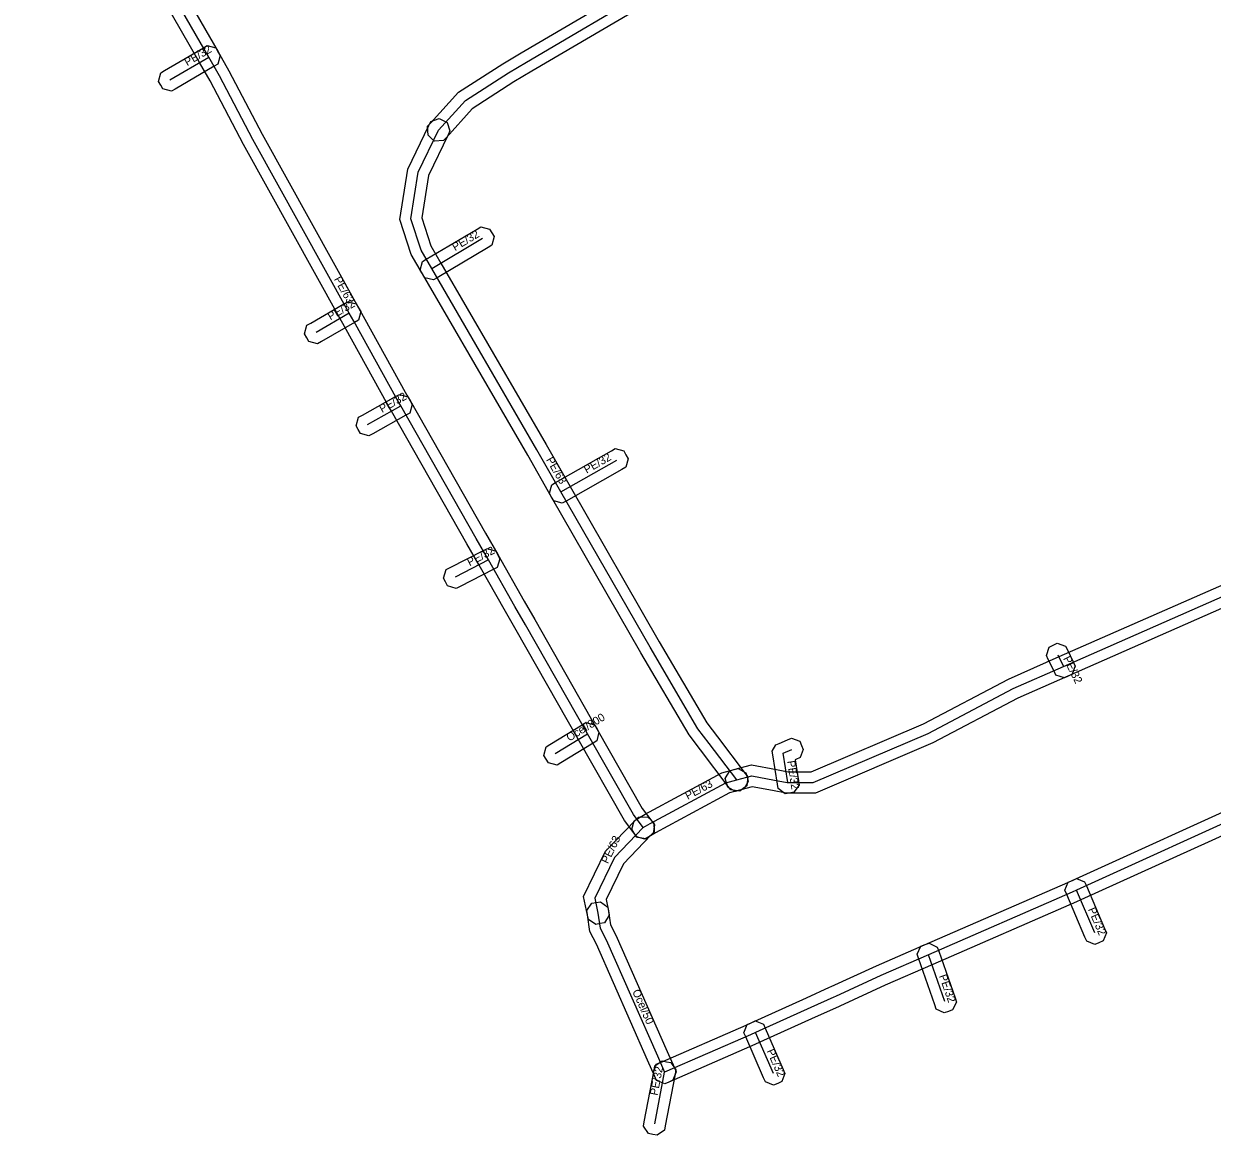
# Model space of a CAD drawing. Extents: x -574390 to -573768, y -1190959 to -1190603.
# Drawn here: x -574091.1 to -573979.8, y -1190806.5 to -1190702.4 of the extents above; entities that cross this region are included whole.
import ezdxf

# ---------------------------------------------------------------- set-up
doc = ezdxf.new("R2010")
doc.units = 0
for name, color, linetype in [('1', 7, 'Continuous'), ('24', 7, 'Continuous'), ('28', 7, 'Continuous'), ('30', 7, 'Continuous')]:
    doc.layers.add(name, color=color, linetype=linetype)

msp = doc.modelspace()

# ---------------------------------------------------------------- linework, layer by layer
at = {"layer": '1'}
for points in [[(-574082.082, -1190689.083), (-574072.923, -1190705.012), (-574071.904, -1190706.788), (-574068.77, -1190712.745), (-574059.755, -1190729.016), (-574059.335, -1190729.776), (-574055.23, -1190737.178), (-574054.932, -1190737.693), (-574047.861, -1190750.125), (-574046.721, -1190752.125), (-574044.241, -1190756.475), (-574043.251, -1190758.215), (-574037.431, -1190768.435), (-574033.173, -1190775.919), (-574032.282, -1190777.097), (-574032.032, -1190777.428), (-574032.146, -1190778.248), (-574032.477, -1190778.498), (-574032.808, -1190778.748), (-574033.628, -1190778.634), (-574033.878, -1190778.303), (-574034.847, -1190777.021), (-574039.169, -1190769.425), (-574044.989, -1190759.205), (-574045.979, -1190757.465), (-574048.459, -1190753.115), (-574049.599, -1190751.115), (-574056.668, -1190738.687), (-574056.97, -1190738.162), (-574061.085, -1190730.744), (-574061.505, -1190729.984), (-574070.53, -1190713.695), (-574073.656, -1190707.752), (-574074.657, -1190706.008), (-574083.818, -1190690.077)], [(-574031.616, -1190699.834), (-574043.513, -1190706.842), (-574045.195, -1190707.831), (-574049.097, -1190710.349), (-574051.529, -1190713.032), (-574051.807, -1190713.339), (-574052.635, -1190713.379), (-574052.942, -1190713.101), (-574053.249, -1190712.823), (-574053.289, -1190711.995), (-574053.011, -1190711.688), (-574050.403, -1190708.811), (-574046.245, -1190706.129), (-574044.527, -1190705.118), (-574032.624, -1190698.106)], [(-573977.067, -1190756.365), (-573993.297, -1190763.515), (-573997.995, -1190765.581), (-574005.96, -1190769.773), (-574016.947, -1190774.481), (-574019.532, -1190774.47), (-574019.707, -1190774.47), (-574020.978, -1190774.222), (-574022.867, -1190773.866), (-574024.053, -1190774.194), (-574024.452, -1190774.304), (-574025.173, -1190773.896), (-574025.284, -1190773.497), (-574025.394, -1190773.098), (-574024.986, -1190772.377), (-574024.587, -1190772.266), (-574022.953, -1190771.814), (-574020.602, -1190772.258), (-574019.511, -1190772.47), (-574017.353, -1190772.479), (-574006.82, -1190767.967), (-573998.865, -1190763.779), (-573994.103, -1190761.685), (-573977.873, -1190754.535)], [(-573974.492, -1190776.493), (-573992.077, -1190784.471), (-573992.504, -1190784.664), (-574005.951, -1190790.527), (-574010.421, -1190792.473), (-574014.657, -1190794.421), (-574014.803, -1190794.486), (-574016.968, -1190795.461), (-574022.156, -1190797.81), (-574022.622, -1190798.023), (-574030.68, -1190801.537), (-574031.06, -1190801.702), (-574031.831, -1190801.399), (-574031.997, -1190801.02), (-574032.162, -1190800.64), (-574031.859, -1190799.869), (-574031.48, -1190799.703), (-574023.438, -1190796.197), (-574022.984, -1190795.99), (-574017.792, -1190793.639), (-574015.623, -1190792.662), (-574015.483, -1190792.599), (-574011.239, -1190790.647), (-574006.749, -1190788.693), (-573993.316, -1190782.836), (-573992.903, -1190782.649), (-573975.308, -1190774.667)]]:
    msp.add_lwpolyline(points, dxfattribs=at)
for points in [[(-574078.292, -1190706.986), (-574077.935, -1190706.777), (-574074.295, -1190704.647), (-574073.938, -1190704.438), (-574073.136, -1190704.648), (-574072.927, -1190705.005), (-574072.718, -1190705.362), (-574072.928, -1190706.164), (-574073.285, -1190706.373), (-574076.925, -1190708.503), (-574077.282, -1190708.712), (-574078.084, -1190708.502), (-574078.293, -1190708.145), (-574078.502, -1190707.788)], [(-574024.865, -1190774.165), (-574025.116, -1190773.835), (-574027.715, -1190770.416), (-574028.791, -1190769.009), (-574033.315, -1190761.312), (-574041.668, -1190746.737), (-574043.907, -1190742.819), (-574053.765, -1190725.821), (-574054.818, -1190724), (-574055.886, -1190720.741), (-574055.124, -1190715.998), (-574053.172, -1190711.927), (-574052.993, -1190711.554), (-574052.211, -1190711.279), (-574051.837, -1190711.458), (-574051.464, -1190711.637), (-574051.189, -1190712.419), (-574051.368, -1190712.793), (-574053.196, -1190716.602), (-574053.834, -1190720.579), (-574052.982, -1190723.18), (-574052.035, -1190724.819), (-574042.173, -1190741.821), (-574039.932, -1190745.743), (-574031.585, -1190760.308), (-574027.129, -1190767.891), (-574026.125, -1190769.204), (-574023.524, -1190772.625), (-574023.273, -1190772.955), (-574023.385, -1190773.775), (-574023.715, -1190774.026), (-574024.045, -1190774.277)], [(-574053.766, -1190724.671), (-574053.41, -1190724.46), (-574048.64, -1190721.63), (-574048.284, -1190721.419), (-574047.481, -1190721.624), (-574047.27, -1190721.98), (-574047.059, -1190722.336), (-574047.264, -1190723.139), (-574047.62, -1190723.35), (-574052.39, -1190726.18), (-574052.746, -1190726.391), (-574053.549, -1190726.186), (-574053.76, -1190725.83), (-574053.971, -1190725.474)], [(-574059.771, -1190730.158), (-574060.129, -1190730.365), (-574063.239, -1190732.165), (-574063.598, -1190732.373), (-574064.398, -1190732.159), (-574064.605, -1190731.801), (-574064.813, -1190731.442), (-574064.599, -1190730.642), (-574064.241, -1190730.435), (-574061.131, -1190728.635), (-574060.772, -1190728.427), (-574059.972, -1190728.641), (-574059.765, -1190728.999), (-574059.557, -1190729.358)], [(-574059.76, -1190739.26), (-574059.398, -1190739.057), (-574056.288, -1190737.317), (-574055.927, -1190737.115), (-574055.13, -1190737.34), (-574054.927, -1190737.702), (-574054.725, -1190738.063), (-574054.95, -1190738.86), (-574055.312, -1190739.063), (-574058.422, -1190740.803), (-574058.783, -1190741.005), (-574059.58, -1190740.78), (-574059.783, -1190740.418), (-574059.985, -1190740.057)], [(-574041.654, -1190745.575), (-574041.294, -1190745.37), (-574036.064, -1190742.4), (-574035.704, -1190742.196), (-574034.905, -1190742.416), (-574034.7, -1190742.776), (-574034.496, -1190743.136), (-574034.716, -1190743.935), (-574035.076, -1190744.14), (-574040.306, -1190747.11), (-574040.666, -1190747.314), (-574041.465, -1190747.094), (-574041.67, -1190746.734), (-574041.874, -1190746.374)], [(-574046.763, -1190753.319), (-574047.131, -1190753.509), (-574050.251, -1190755.119), (-574050.619, -1190755.309), (-574051.409, -1190755.057), (-574051.599, -1190754.689), (-574051.789, -1190754.321), (-574051.537, -1190753.531), (-574051.169, -1190753.341), (-574048.049, -1190751.731), (-574047.681, -1190751.541), (-574046.891, -1190751.793), (-574046.701, -1190752.161), (-574046.511, -1190752.529)], [(-573993.525, -1190760.687), (-573993.342, -1190761.059), (-573992.802, -1190762.159), (-573992.62, -1190762.531), (-573992.887, -1190763.315), (-573993.259, -1190763.498), (-573993.631, -1190763.68), (-573994.415, -1190763.413), (-573994.598, -1190763.041), (-573995.138, -1190761.941), (-573995.32, -1190761.569), (-573995.053, -1190760.785), (-573994.681, -1190760.602), (-573994.309, -1190760.42)], [(-574042.194, -1190770.131), (-574041.84, -1190769.916), (-574038.82, -1190768.076), (-574038.466, -1190767.861), (-574037.661, -1190768.056), (-574037.446, -1190768.41), (-574037.231, -1190768.764), (-574037.426, -1190769.569), (-574037.78, -1190769.784), (-574040.8, -1190771.624), (-574041.154, -1190771.839), (-574041.959, -1190771.644), (-574042.174, -1190771.29), (-574042.389, -1190770.936)], [(-574020.454, -1190774.034), (-574020.518, -1190773.625), (-574020.948, -1190770.885), (-574021.001, -1190770.546), (-574020.67, -1190769.946), (-574020.355, -1190769.811), (-574019.565, -1190769.471), (-574019.185, -1190769.307), (-574018.415, -1190769.614), (-574018.251, -1190769.995), (-574018.087, -1190770.375), (-574018.394, -1190771.145), (-574018.775, -1190771.309), (-574018.852, -1190771.342), (-574018.542, -1190773.315), (-574018.478, -1190773.724), (-574018.966, -1190774.394), (-574019.375, -1190774.458), (-574019.784, -1190774.522)], [(-574033.946, -1190777.05), (-574033.589, -1190776.839), (-574032.912, -1190776.439), (-574025.732, -1190772.575), (-574024.58, -1190772.264), (-574024.18, -1190772.156), (-574023.462, -1190772.57), (-574023.354, -1190772.97), (-574023.246, -1190773.37), (-574023.66, -1190774.088), (-574024.06, -1190774.196), (-574024.988, -1190774.445), (-574031.928, -1190778.181), (-574032.571, -1190778.561), (-574032.928, -1190778.772), (-574033.73, -1190778.566), (-574033.941, -1190778.209), (-574034.152, -1190777.852)], [(-574032.073, -1190778.096), (-574032.36, -1190778.394), (-574034.949, -1190781.079), (-574036.572, -1190784.431), (-574036.351, -1190785.509), (-574036.267, -1190785.915), (-574036.723, -1190786.606), (-574037.129, -1190786.689), (-574037.535, -1190786.773), (-574038.226, -1190786.317), (-574038.309, -1190785.911), (-574038.668, -1190784.169), (-574036.611, -1190779.921), (-574033.8, -1190777.006), (-574033.513, -1190776.708), (-574032.684, -1190776.693), (-574032.386, -1190776.98), (-574032.088, -1190777.267)], [(-573991.537, -1190788.334), (-573991.7, -1190787.953), (-573993.41, -1190783.953), (-573993.573, -1190783.572), (-573993.264, -1190782.803), (-573992.883, -1190782.64), (-573992.502, -1190782.477), (-573991.733, -1190782.786), (-573991.57, -1190783.167), (-573989.86, -1190787.167), (-573989.697, -1190787.548), (-573990.006, -1190788.317), (-573990.387, -1190788.48), (-573990.768, -1190788.643)], [(-574036.406, -1190785.147), (-574036.342, -1190785.556), (-574036.147, -1190786.808), (-574035.656, -1190787.771), (-574030.848, -1190798.667), (-574030.165, -1190800.217), (-574029.998, -1190800.596), (-574030.298, -1190801.368), (-574030.677, -1190801.535), (-574031.056, -1190801.702), (-574031.828, -1190801.402), (-574031.995, -1190801.023), (-574032.678, -1190799.475), (-574037.464, -1190788.629), (-574038.073, -1190787.432), (-574038.318, -1190785.864), (-574038.382, -1190785.455), (-574037.893, -1190784.786), (-574037.484, -1190784.722), (-574037.075, -1190784.658)], [(-574005.627, -1190794.701), (-574005.764, -1190794.31), (-574007.294, -1190789.94), (-574007.431, -1190789.549), (-574007.071, -1190788.803), (-574006.68, -1190788.666), (-574006.289, -1190788.529), (-574005.543, -1190788.889), (-574005.406, -1190789.28), (-574003.876, -1190793.65), (-574003.739, -1190794.041), (-574004.099, -1190794.787), (-574004.49, -1190794.924), (-574004.881, -1190795.061)], [(-574021.641, -1190801.529), (-574021.807, -1190801.15), (-574023.487, -1190797.3), (-574023.652, -1190796.92), (-574023.349, -1190796.149), (-574022.97, -1190795.983), (-574022.59, -1190795.818), (-574021.819, -1190796.121), (-574021.653, -1190796.5), (-574019.973, -1190800.35), (-574019.808, -1190800.73), (-574020.111, -1190801.501), (-574020.49, -1190801.667), (-574020.87, -1190801.832)], [(-574033.07, -1190805.678), (-574032.992, -1190805.271), (-574032.062, -1190800.431), (-574031.984, -1190800.024), (-574031.298, -1190799.56), (-574030.891, -1190799.638), (-574030.484, -1190799.716), (-574030.02, -1190800.402), (-574030.098, -1190800.809), (-574031.028, -1190805.649), (-574031.106, -1190806.056), (-574031.792, -1190806.52), (-574032.199, -1190806.442), (-574032.606, -1190806.364)]]:
    msp.add_lwpolyline(points, close=True, dxfattribs=at)
at = {"layer": '24'}
for points in [[(-574052.27, -1190712.36), (-574049.75, -1190709.58), (-574045.72, -1190706.98), (-574044.02, -1190705.98), (-574032.12, -1190698.97), (-574018.83, -1190691.28), (-574010.79, -1190686.63), (-574001.67, -1190681.44), (-573999.27, -1190680.08), (-573995.75, -1190678.11), (-573983.73, -1190671.39), (-573975.99, -1190667.06), (-573969.47, -1190663.41), (-573965.82, -1190661.37), (-573959.87, -1190658), (-573951.88, -1190653.46), (-573950.37, -1190652.6), (-573943.33, -1190648.61), (-573936.84, -1190644.93), (-573934.69, -1190643.69), (-573928.142665, -1190639.934461)], [(-574033.08, -1190777.7), (-574034.01, -1190776.47), (-574038.3, -1190768.93), (-574044.12, -1190758.71), (-574045.11, -1190756.97), (-574047.59, -1190752.62), (-574048.73, -1190750.62), (-574055.8, -1190738.19), (-574056.1, -1190737.67), (-574060.21, -1190730.26), (-574060.63, -1190729.5), (-574069.65, -1190713.22), (-574072.78, -1190707.27), (-574073.79, -1190705.51), (-574082.95, -1190689.58), (-574087.13, -1190682.24), (-574091.12, -1190675.23)], [(-574077.43, -1190707.64), (-574073.79, -1190705.51)], [(-574024.32, -1190773.23), (-574026.92, -1190769.81), (-574027.96, -1190768.45), (-574032.45, -1190760.81), (-574040.8, -1190746.24), (-574043.04, -1190742.32), (-574052.9, -1190725.32), (-574053.9, -1190723.59), (-574054.86, -1190720.66), (-574054.16, -1190716.3), (-574052.27, -1190712.36)], [(-574060.63, -1190729.5), (-574063.74, -1190731.3)], [(-574058.91, -1190739.93), (-574055.8, -1190738.19)], [(-574040.8, -1190746.24), (-574035.57, -1190743.27)], [(-574024.32, -1190773.23), (-574022.91, -1190772.84), (-574020.79, -1190773.24), (-574019.61, -1190773.47), (-574019.53, -1190773.47), (-574017.15, -1190773.48), (-574006.39, -1190768.87), (-573998.43, -1190764.68), (-573993.7, -1190762.6), (-573977.47, -1190755.45)], [(-573994.24, -1190761.5), (-573993.7, -1190762.6)], [(-574033.08, -1190777.7), (-574032.42, -1190777.31), (-574025.36, -1190773.51), (-574024.32, -1190773.23)], [(-573974.9, -1190775.58), (-573992.49, -1190783.56), (-573992.91, -1190783.75), (-574006.35, -1190789.61), (-574010.83, -1190791.56), (-574015.07, -1190793.51), (-574015.213, -1190793.574), (-574017.38, -1190794.55), (-574022.57, -1190796.9), (-574023.03, -1190797.11), (-574031.08, -1190800.62)], [(-574033.08, -1190777.7), (-574035.78, -1190780.5), (-574037.62, -1190784.3), (-574037.33, -1190785.71)], [(-574037.33, -1190785.71), (-574037.11, -1190787.12), (-574036.56, -1190788.2), (-574031.763, -1190799.071), (-574031.08, -1190800.62)], [(-574020.89, -1190800.75), (-574022.57, -1190796.9)]]:
    msp.add_lwpolyline(points, dxfattribs=at)
at = {"layer": '28'}
for points in [[(-574052.9, -1190725.32), (-574048.13, -1190722.49)], [(-574047.59, -1190752.62), (-574050.71, -1190754.23)], [(-574041.32, -1190770.77), (-574038.3, -1190768.93)], [(-574019.53, -1190773.47), (-574019.96, -1190770.73), (-574019.17, -1190770.39)], [(-573990.78, -1190787.56), (-573992.49, -1190783.56)], [(-574004.82, -1190793.98), (-574006.35, -1190789.61)], [(-574032.01, -1190805.46), (-574031.08, -1190800.62)]]:
    msp.add_lwpolyline(points, dxfattribs=at)

# ---------------------------------------------------------------- texts
at = {"layer": '30'}
for s, rotation, p in [('PE/32', 30.33466996, (-574075.81, -1190706.375)), ('PE/32', 30.68029178, (-574050.715, -1190723.705)), ('PE/63', 298.98882252, (-574062.082904, -1190726.31671)), ('PE/32', 30.06132008, (-574062.385, -1190730.2)), ('PE/32', 29.22638161, (-574057.555, -1190738.86)), ('PE/63', 299.7448813, (-574042.205401, -1190743.230548)), ('PE/32', 29.59127368, (-574038.385, -1190744.555)), ('PE/32', 27.29489424, (-574049.35, -1190753.225)), ('PE/32', 296.14684124, (-573993.77, -1190761.85)), ('Ocel/800', 31.35276167, (-574040.01, -1190769.65)), ('PE/32', 278.91892862, (-574019.61167, -1190771.475171)), ('PE/63', 28.29107579, (-574028.909303, -1190775.112741)), ('PE/63', 64.16324578, (-574036.387878, -1190781.142356)), ('PE/32', 293.14670784, (-573991.435, -1190785.36)), ('PE/32', 289.29588617, (-574005.385, -1190791.595)), ('Ocel/50', 293.81022543, (-574034.132299, -1190793.048435)), ('PE/32', 293.5747062, (-574021.53, -1190798.625)), ('PE/32', 79.12325458, (-574031.745, -1190802.84))]:
    msp.add_text(s, height=0.75, rotation=rotation, dxfattribs=at).set_placement(p)

doc.saveas('drawing.dxf')
